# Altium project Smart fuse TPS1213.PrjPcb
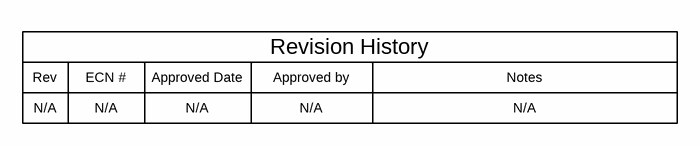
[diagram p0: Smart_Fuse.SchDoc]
TID: TIDA-020065; TechSupport: http://www.ti.com/support; SCH_Rev: E2; PRJ_Title: TPS1213-Q1+INA; PRJ_Number: TIDA-020065; PRJ_Engineer: David Martinez; PRJ_Customer: Public Release; PCB_Rev: E2; PCB_Layout: David Martinez; CopyrightYear: 2023
4 sheets, 114 parts. Net scope: global (net labels, ports and power ports of the same name join across sheets).
Board file: Smart_Fuse.PcbDoc
Sheets:
  Smart_Fuse.SchDoc
  Smart_Fuse_Schematic.SchDoc
  Smart_Fuse_MCU_Schematic.SchDoc
  Smart_Fuse_Hardware.SchDoc

## Sheet Smart_Fuse.SchDoc
size 431 x 279 mm; Date: Not shown in title block; ApprovedBy: Not shown in title block; CheckedBy: Not shown in title block; Author: Not shown in title block; CompanyName: Not shown in title block; Engineer: Not shown in title block; Organization: Not shown in title block; Address1: Not shown in title block; Address2: Not shown in title block; Address3: Not shown in title block; Address4: Not shown in title block; DocumentNumber: 1; Revision: Use project parameter SCH_Rev; SheetNumber: 1; SheetTotal: 4; PageSetup: Record=PageOptions¦CenterHorizontal=True¦CenterVertical=True¦PrintScale=1.00¦XCorrection=1.00¦YCorrection=1.00¦PrintKind=0¦BorderSize=5000000¦LeftOffset=0¦BottomOffset=0¦Orientation=2¦PaperLength=1000¦PaperWidth=1000¦Scale=100¦PaperSource=15¦PrintQuality=600¦MediaType=1¦DitherType=10¦PaperKind=Letter¦PrintScaleMode=1

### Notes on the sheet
- Rev
- N/A
- ECN #
- Approved Date
- Approved by
- Revision History
- Notes

## Sheet Smart_Fuse_Schematic.SchDoc: Main Page
size 431 x 279 mm; Date: Not shown in title block; ApprovedBy: Not shown in title block; CheckedBy: Not shown in title block; Author: Not shown in title block; CompanyName: Not shown in title block; DrawnBy: David Martinez; Engineer: Not shown in title block; Organization: Not shown in title block; Address1: Not shown in title block; Address2: Not shown in title block; Address3: Not shown in title block; Address4: Not shown in title block; DocumentNumber: 2; Revision: Use project parameter SCH_Rev; SheetNumber: 2; SheetTotal: 4; PageSetup: Record=PageOptions¦CenterHorizontal=True¦CenterVertical=True¦PrintScale=1.00¦XCorrection=1.00¦YCorrection=1.00¦PrintKind=0¦BorderSize=5000000¦LeftOffset=0¦BottomOffset=0¦Orientation=2¦PaperLength=1000¦PaperWidth=1000¦Scale=100¦PaperSource=15¦PrintQuality=600¦MediaType=1¦DitherType=10¦PaperKind=Letter¦PrintScaleMode=1
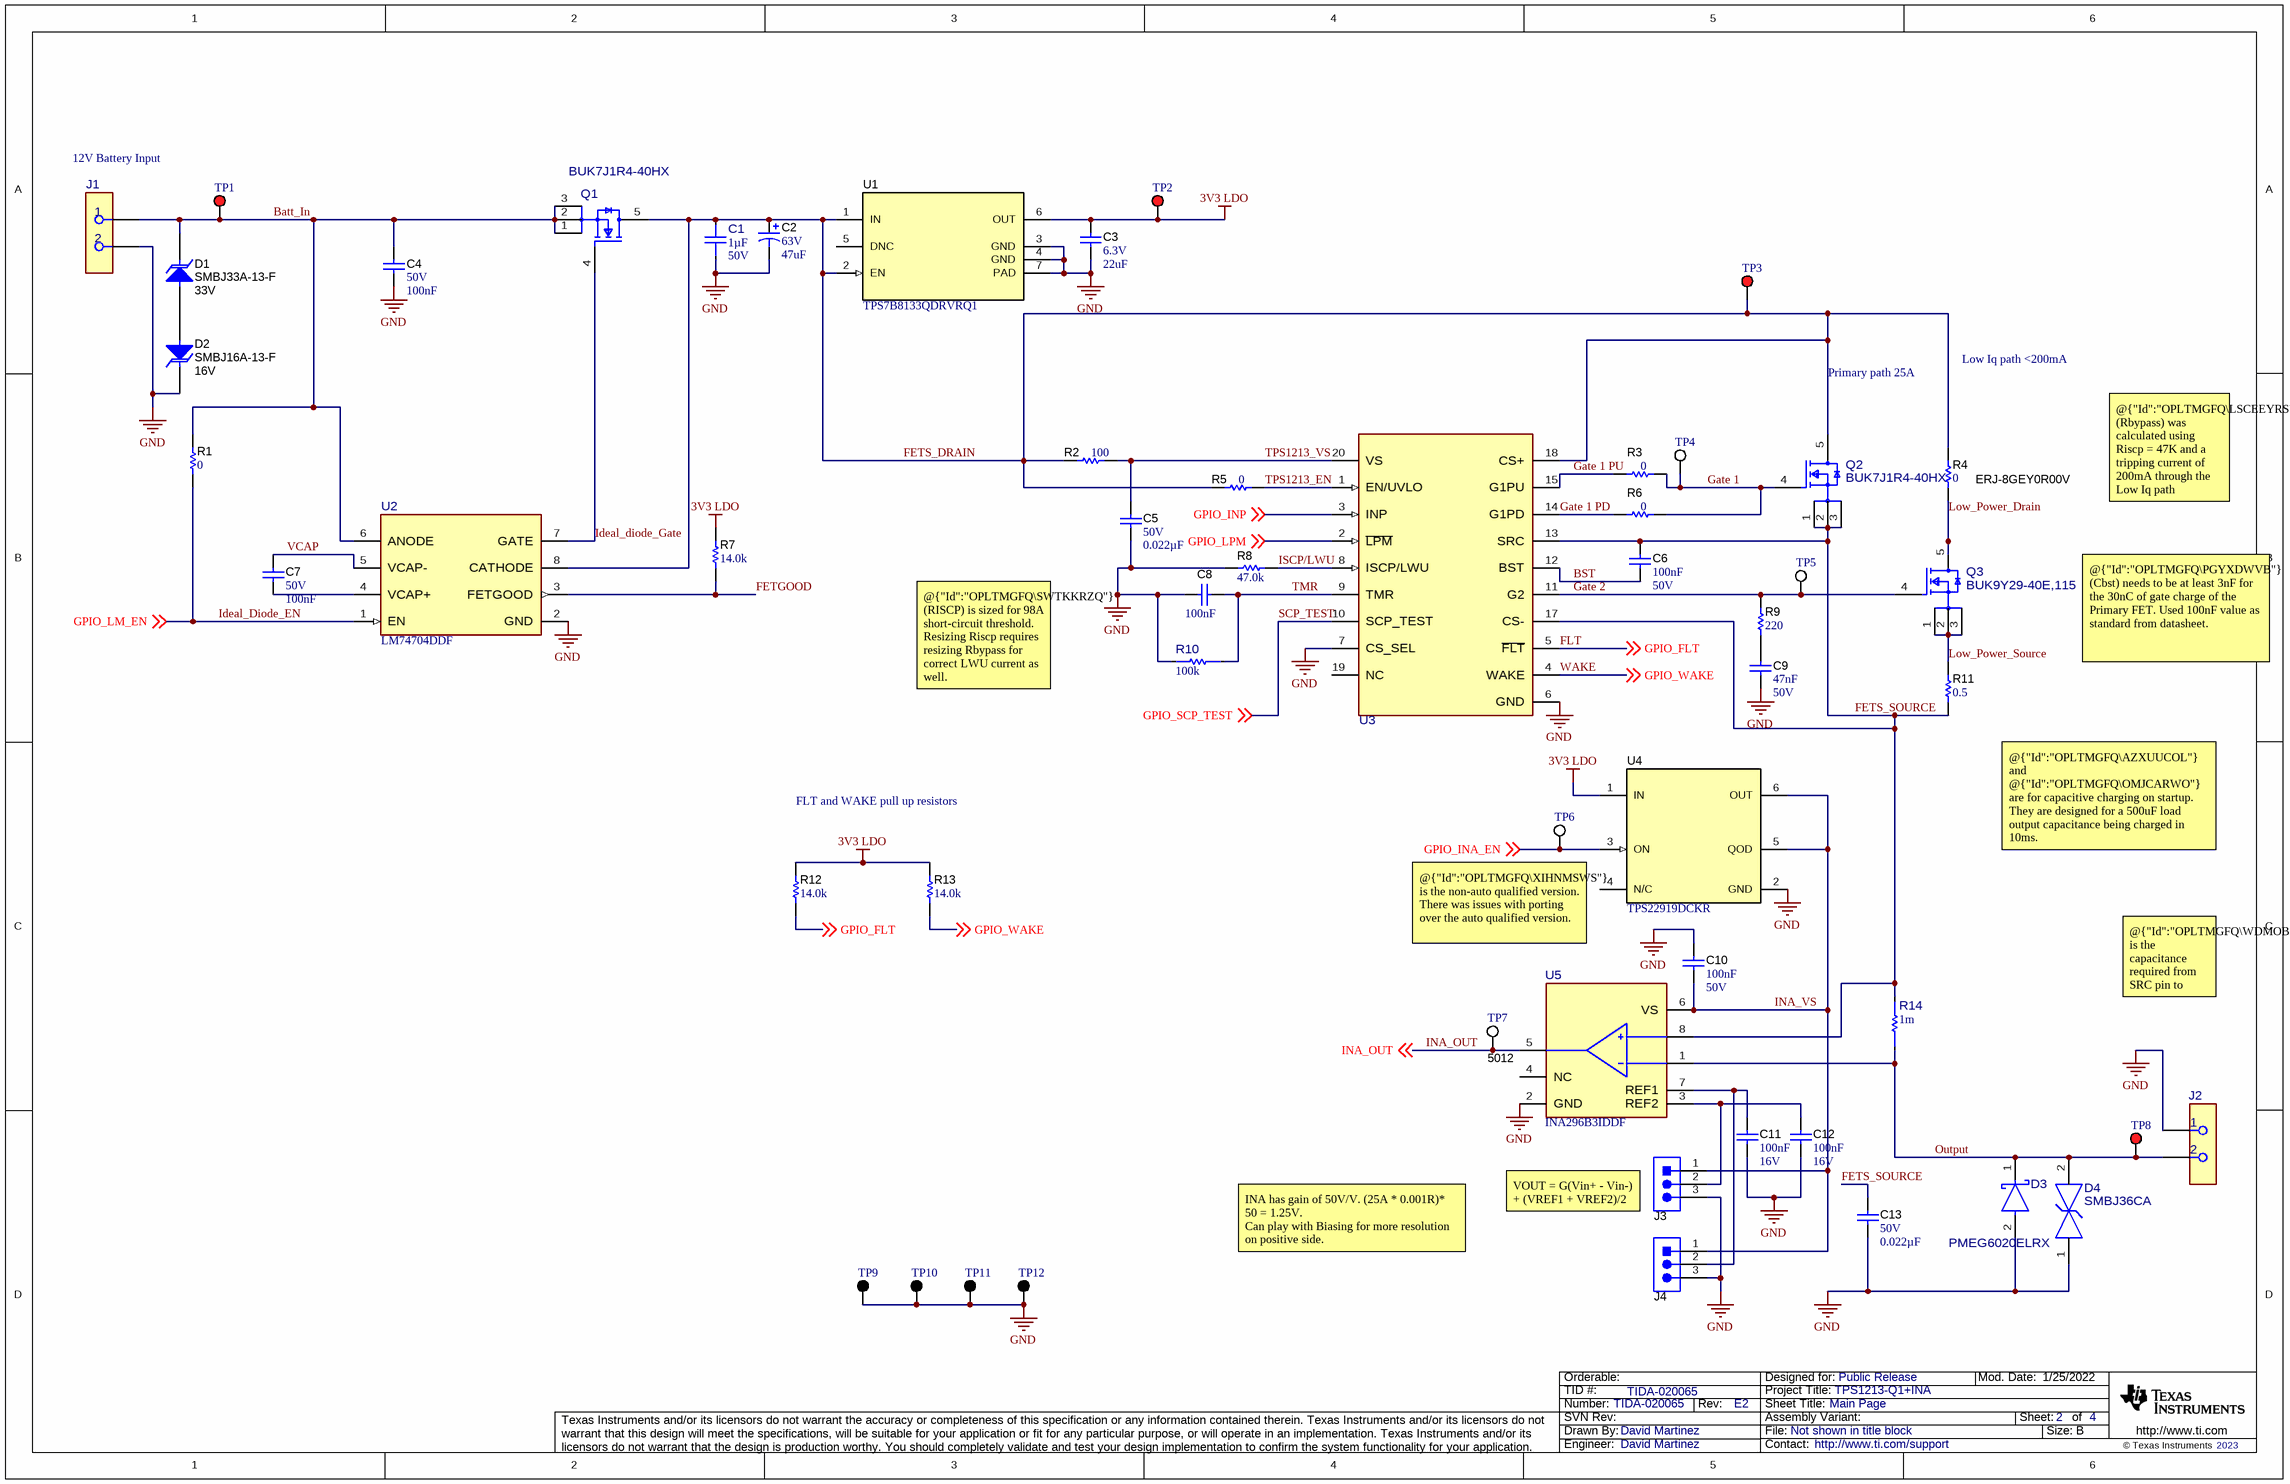
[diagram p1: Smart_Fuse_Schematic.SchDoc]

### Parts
C1  Cap_F: 1µF  VDC_V: 50V  [FP-UMK212B7105KGHT_0805-MFG]  (hidden comment: UMK212B7105KGHT)
C2  VDC_V: 63V  ValueDisplayed: 47uF  [SM_RADIAL_F]  (hidden comment: EEE-FK1J470P)
C3  VDC_V: 6.3V  ValueDisplayed: 22uF  [0805_HV]  (hidden comment: GCM21BD70J226ME36L)
C4  VDC_V: 50V  Cap_F: 100nF  [0603L]  (hidden comment: 06035C104K4Z4A)
C5  VDC_V: 50V  ValueDisplayed: 0.022µF  [0805_HV]  (hidden comment: CGA4J2C0G1H223J125AA)
C6  Cap_F: 100nF  VDC_V: 50V  [0603]  (hidden comment: 06035C104KAZ2A)
C7  VDC_V: 50V  Cap_F: 100nF  [0603L]  (hidden comment: 06035C104K4Z4A)
C8  Cap_F: 100nF  [0603]  (hidden comment: 06035C104KAZ2A)
C9  Cap_F: 47nF  VDC_V: 50V  [0603]  (hidden comment: CGA3E2X7R1H473K080AA)
C10  Cap_F: 100nF  VDC_V: 50V  [0603L]  (hidden comment: 06035C104KAZ2A)
C11  Cap_F: 100nF  VDC_V: 16V  [0603L]  (hidden comment: GRM188R71C104KA01D)
C12  Cap_F: 100nF  VDC_V: 16V  [0603L]  (hidden comment: GRM188R71C104KA01D)
C13  VDC_V: 50V  ValueDisplayed: 0.022µF  [0805_HV]  (hidden comment: CGA4J2C0G1H223J125AA)
D1  SMBJ33A-13-F  value 33V  [SMB]
D2  SMBJ16A-13-F  value 16V  [SMB]
D3  PMEG6020ELRX  [FP-PMEG6020ELRX_SOD123W-MFG]
D4  SMBJ36CA  [FP-SMBJ36CA_DO-214AA-0]
J1  691256610002  [FP-691256610002_HDR2-MFG]  (value not drawn)
J2  691256610002  [FP-691256610002_HDR2-MFG]  (value not drawn)
J3  TSW-103-07-T-S  [Samtec_TSW-103-07-T-S]  (value not drawn)
J4  TSW-103-07-T-S  [Samtec_TSW-103-07-T-S]  (value not drawn)
Q1  BUK7J1R4-40HX  [FP-BUK7J1R4-40HX_LFPAK56E-MFG]
Q2  BUK7J1R4-40HX  [FP-BUK7J1R4-40HX_LFPAK56E-MFG]
Q3  BUK9Y29-40E,115  [FP-BUK9Y29-40E,115_LFPAK56-MFG]
R1  ValueDisplayed: 0  [0603]  (hidden comment: ERJ-3GEY0R00V)
R2  ValueDisplayed: 100  [0603]  (hidden comment: RMCP0603JT100R)
R3  ValueDisplayed: 0  [0603]  (hidden comment: ERJ-3GEY0R00V)
R4  ERJ-8GEY0R00V  ValueDisplayed: 0  [1206]
R5  ValueDisplayed: 0  [0603]  (hidden comment: ERJ-3GEY0R00V)
R6  ValueDisplayed: 0  [0603]  (hidden comment: ERJ-3GEY0R00V)
R7  ValueDisplayed: 14.0k  [0603]  (hidden comment: CRCW060314K0FKEA)
R8  ValueDisplayed: 47.0k  [0603]  (hidden comment: RG1608P-473-B-T5)
R9  ValueDisplayed: 220  [0603]  (hidden comment: CRCW0603220RJNEA)
R10  value 100k  [FP-ERJ-PB3B1003V_0603-IPC_A]  (hidden comment: ERJ-PB3B1003V)
R11  ValueDisplayed: 0.5  [1206]  (hidden comment: CSR1206FKR500)
R12  ValueDisplayed: 14.0k  [0603]  (hidden comment: CRCW060314K0FKEA)
R13  ValueDisplayed: 14.0k  [0603]  (hidden comment: CRCW060314K0FKEA)
R14  Res_ohm: 1m  [FP-WSLF25121L000FEB_2512-MFG]  (hidden comment: WSLF25121L000FEB)
TP1  5010  [Keystone5010]  (value not drawn)
TP2  5010  [Keystone5010]  (value not drawn)
TP3  5010  [Keystone5010]  (value not drawn)
TP4  5012  [Keystone5012]  (value not drawn)
TP5  5012  [Keystone5012]  (value not drawn)
TP6  5012  [Keystone5012]  (value not drawn)
TP7  5012  [Keystone5012]
TP8  5010  [Keystone5010]  (value not drawn)
TP9  5011  [Keystone5011]  (value not drawn)
TP10  5011  [Keystone5011]  (value not drawn)
TP11  5011  [Keystone5011]  (value not drawn)
TP12  5011  [Keystone5011]  (value not drawn)
U1  TPS7B8133QDRVRQ1  [DRV0006A]
U2  LM74704DDF  [DDF0008A-MFG]
U3  TPS12130QDGXRQ1  [DGX0019A-MFG]  (value not drawn)
U4  TPS22919DCKR  [DCK0006A_N]
U5  INA296B3IDDF  [DDF0008A-MFG]

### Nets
3V3 LDO: C3.1 R7.2 R12.2 R13.2 TP2.1 U1.6(OUT) U4.1(IN)
GND: C1.1 C2.2(-) C3.2 C4.2 C5.2 C8.2 C9.2 C10.1 C11.2 C12.2 C13.2 D2.1(K) D3.2(ANODE) D4.1 J1.2 J2.1 J3.3 J4.3 R8.1 R10.2 TP9.1 TP10.1 TP11.1 TP12.1 U1.3(GND) U1.4(GND) U1.7(PAD) U2.2(GND) U3.6(GND) U3.7(CS_SEL) U4.2(GND) U5.2(GND)
Batt_In: C4.1 D1.1(K) J1.1 Q1.1(S) Q1.2(S) Q1.3(S) R1.2 TP1.1 U2.6(ANODE)
BST: C6.2 U3.12(BST)
FETGOOD: R7.1 U2.3(FETGOOD)
FETS_DRAIN: C1.2 C2.1(+) Q1.5(D) Q2.5(D) R2.1 R4.2 R5.1 TP3.1 U1.1(IN) U1.2(EN) U2.8(CATHODE) U3.18(CS+)
FETS_SOURCE: C6.1 C13.1 Q2.1(S) Q2.2(S) Q2.3(S) R11.1 R14.2 U3.13(SRC) U3.17(CS-) U5.8(IN+)
FLT: R12.1 U3.5(~{FLT}) ; off-sheet GPIO_FLT  [also labelled GPIO_FLT]
Gate 1: Q2.4(G) R3.2 R6.2 TP4.1
Gate 1 PD: R6.1 U3.14(G1PD)
Gate 1 PU: R3.1 U3.15(G1PU)
Gate 2: Q3.4(G) R9.2 TP5.1 U3.11(G2)
GPIO_INA_EN: TP6.1 U4.3(ON) ; off-sheet GPIO_INA_EN
GPIO_INP: U3.3(INP) ; off-sheet GPIO_INP
GPIO_LPM: U3.2(~{LPM}) ; off-sheet GPIO_LPM
GPIO_SCP_TEST: U3.10(SCP_TEST) ; off-sheet GPIO_SCP_TEST  [also labelled SCP_TEST]
GPIO_WAKE: R13.1 U3.4(WAKE) ; off-sheet GPIO_WAKE  [also labelled WAKE]
Ideal_Diode_EN: R1.1 U2.1(EN) ; off-sheet GPIO_LM_EN  [also labelled GPIO_LM_EN]
Ideal_diode_Gate: Q1.4(G) U2.7(GATE)
INA_OUT: TP7.1 U5.5(OUT) ; off-sheet INA_OUT
INA_VS: C10.2 J3.1 J4.1 U4.5(QOD) U4.6(OUT) U5.6(VS)
ISCP/LWU: R8.2 U3.8(ISCP/LWU)
Low_Power_Drain: Q3.5(D) R4.1
Low_Power_Source: Q3.1(S) Q3.2(S) Q3.3(S) R11.2
Output: D3.1(CATHODE) D4.2 J2.2 R14.1 TP8.1 U5.1(IN-)
TMR: C8.1 R10.1 U3.9(TMR)
TPS1213_EN: R5.2 U3.1(EN/UVLO)
TPS1213_VS: C5.1 R2.2 U3.20(VS)
VCAP: C7.1 U2.5(VCAP-)
NetC7_2: C7.2 U2.4(VCAP+)
NetC9_1: C9.1 R9.1
NetC11_1: C11.1 J4.2 U5.7(REF1)
NetC12_1: C12.1 J3.2 U5.3(REF2)
NetD1_2: D1.2(A) D2.2(A)

Not connected (* = marked no-connect by the designer): U1 5(DNC); U3 19(NC); U4 4(N/C); U5 4(NC)

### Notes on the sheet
- 12V Battery Input
- Low Iq path <200mA
- Primary path 25A
- @{"Id":"OPLTMGFQ\LSCEEYRS"} (Rbypass) was calculated using Riscp = 47K and a tripping current of 200mA through the Low Iq path
- @{"Id":"OPLTMGFQ\SWTKKRZQ"} (RISCP) is sized for 98A short-circuit threshold. Resizing Riscp requires resizing Rbypass for correct LWU current as well.
- @{"Id":"OPLTMGFQ\PGYXDWVB"} (Cbst) needs to be at least 3nF for the 30nC of gate charge of the Primary FET. Used 100nF value as standard from datasheet.
- FLT and WAKE pull up resistors
- @{"Id":"OPLTMGFQ\AZXUUCOL"} and @{"Id":"OPLTMGFQ\OMJCARWO"} are for capacitive charging on startup. They are designed for a 500uF load output capacitance being charged in 10ms.
- @{"Id":"OPLTMGFQ\XIHNMSWS"} is the non-auto qualified version. There was issues with porting over the auto qualified version.
- @{"Id":"OPLTMGFQ\WDMOBPKS"} is the capacitance required from SRC pin to GND.
- VOUT = G(Vin+ - Vin-) + (VREF1 + VREF2)/2
- INA has gain of 50V/V. (25A * 0.001R)* 50 = 1.25V.
  Can play with Biasing for more resolution on positive side.

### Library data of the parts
C1 = CMP-0098253-1: Multilayer Ceramic Capacitor 1 uF 50V X7R 10% SMD 0805 Automotive T/R; Manufacturer: Taiyo Yuden; Tolerance_%: 0.1%; AEC Qualified: Yes; SizeZ_mm: 1.35mm; ValueDisplayed: 1uF; Value: 1µF; TempCo: 0.15; AEC Grade: Grade 1
C2 = CMP-0011192-2: CAP, AL, 47 uF, 63 V, +/- 20%, 0.65 ohm, AEC-Q200 Grade 2, SMD; Manufacturer: Panasonic; TaMin_C: -55°C; ESR_ohm: 6.5d; Polarized: Y; SizeAreaWB_mm2: 123.6; U/M: EA; Value: 47uF; TaMax_C: 105°C; SizeZ_mm: 10.2; SizeX_mm: 10; SizeY_mm: 8.3; Cap_Case: F; SizeArea_mm2: 83; CompType: Capacitor; Cap_F: 47µF; IRMS_A: 2.5dA; AEC Grade: 2; AEC Category: Q200
C3 = CMP-0008015-1: CAP, CERM, 22 uF, 6.3 V, +/- 20%, X7T, AEC-Q200 Grade 1, 0805; Manufacturer: MuRata; TaMin_C: -55°C; Polarized: N; SizeAreaWB_mm2: 6.75; Value1: Unknown; U/M: EA; Value: 22uF; TaMax_C: 125°C; SizeZ_mm: 1.45; SizeX_mm: 2; SizeY_mm: 1.25; Cap_Case: 0805; SizeArea_mm2: 2.5; AEC Qualified: Y; Cap_F: 22µF; AEC Grade: 1; AEC Category: Q200
C4 C7 = CMP-0084736-1: CAP, CERM, 0.1 µF, 50 V,+/- 10%, X7R, AEC-Q200 Grade 0, 0603; Manufacturer: AVX; SizeX_mm: 1.6; AEC Qualified: Y; Value: 0.1uF; TaMin_C: -55°C; TaMax_C: 125°C; SizeY_mm: 0.8; SizeAreaWB_mm2: 4.68; AEC Grade: 0; SizeArea_mm2: 1.28; SizeZ_mm: 1; ValueDisplayed: 0.1µF; U/M: EA; Cap_Case: 0603; Polarized: N; AEC Category: Q200
C5 C13 = CMP-0079608-1: CAP, CERM, 0.022 µF, 50 V,+/- 5%, C0G/NP0, AEC-Q200 Grade 1, 0805; Manufacturer: TDK; TaMin_C: -55°C; Polarized: N; SizeAreaWB_mm2: 6.75; U/M: EA; Value: 0.022uF; TaMax_C: 125°C; SizeZ_mm: 1.45; SizeX_mm: 2; SizeY_mm: 1.25; Cap_Case: 0805; SizeArea_mm2: 2.5; AEC Qualified: Y; Cap_F: 22nF; AEC Grade: 1; AEC Category: Q200
C6 = CMP-0079095-1: CAP, CERM, 0.1 µF, 50 V,+/- 10%, X7R, AEC-Q200 Grade 1, 0603; Manufacturer: AVX; SizeAreaWB_mm2: 4.68; SizeArea_mm2: 1.28; AEC Qualified: Y; AEC Category: Q200; Value: 0.1uF; TaMax_C: 125°C; SizeZ_mm: 1; Polarized: N; TaMin_C: -55°C; SizeY_mm: 0.8; U/M: EA; SizeX_mm: 1.6; ValueDisplayed: 0.1µF
C8 = CMP-0079095-1: CAP, CERM, 0.1 µF, 50 V,+/- 10%, X7R, AEC-Q200 Grade 1, 0603; Manufacturer: AVX; SizeAreaWB_mm2: 4.68; SizeArea_mm2: 1.28; AEC Qualified: Y; AEC Category: Q200; Value: 0.1uF; TaMax_C: 125°C; SizeZ_mm: 1; Polarized: N; TaMin_C: -55°C; VDC_V: 50V; SizeY_mm: 0.8; U/M: EA; SizeX_mm: 1.6; ValueDisplayed: 0.1µF
C9 = CMP-0007079-4: CAP, CERM, 0.047 uF, 50 V, +/- 10%, X7R, AEC-Q200 Grade 1, 0603; Manufacturer: TDK; TaMin_C: -55°C; ESR_ohm: 49.007m; Polarized: N; SizeAreaWB_mm2: 4.68; Value1: 0.049007 ohm; U/M: EA; TaMax_C: 125°C; SizeZ_mm: 1; SizeX_mm: 1.6; SizeY_mm: 0.8; SizeArea_mm2: 1.28; AEC Qualified: Y; IRMS_A: 767.528mA; AEC Category: Q200
C10 = CMP-0079095-1: CAP, CERM, 0.1 µF, 50 V,+/- 10%, X7R, AEC-Q200 Grade 1, 0603; Manufacturer: AVX; SizeAreaWB_mm2: 4.68; SizeArea_mm2: 1.28; AEC Qualified: Y; AEC Category: Q200; Value: 0.1uF; TaMax_C: 125°C; SizeZ_mm: 1; Polarized: N; TaMin_C: -55°C; SizeY_mm: 0.8; U/M: EA; SizeX_mm: 1.6; Cap_Case: 0603; ValueDisplayed: 0.1µF
C11 C12 = CMP-0007378-5: CAP, CERM, 0.1 uF, 16 V, +/- 10%, X7R, 0603; Manufacturer: MuRata; TaMin_C: -55°C; Polarized: N; SizeAreaWB_mm2: 4.68; Value1: Unknown; U/M: EA; Value: 0.1uF; TaMax_C: 125°C; SizeZ_mm: 1; SizeX_mm: 1.6; SizeY_mm: 0.8; Cap_Case: 0603; SizeArea_mm2: 1.28; AEC Category: Q200
D1 = CMP-0005563-4: Diode, TVS, Uni, 33 V, 53.3 Vc, SMB; Manufacturer: Diodes Inc.; Vc: 53.3V; Value1: 600W; Vbr_Max: 42.2V; Vbr_Min: 36.7V; SizeX_mm: 5.6; SizeAreaWB_mm2: 44.156; AEC Category: Q101; SizeY_mm: 3.81; SizeZ_mm: 2.6; Ipp: 11.3A; SizeArea_mm2: 21.336
D2 = CMP-0005547-4: Diode, TVS, Uni, 16 V, 26 Vc, SMB; Manufacturer: Diodes Inc.; SizeArea_mm2: 21.336; SizeY_mm: 3.81; Vbr_Min: 17.8V; Ppk: 600W; AEC Category: Q101; SizeZ_mm: 2.6; Ipp: 23.1A; SizeAreaWB_mm2: 44.156; Vc: 26V; Vbr_Max: 20.5V; SizeX_mm: 5.6
D3 = CMP-0090247-1: Diode Schottky 60V 2A Surface Mount CFP3; Manufacturer: Nexperia; Cap_F: 110pF; SizeZ_mm: 1.1mm; TJmax_C: 175°C; AEC Grade: Grade 0; Forward Current: 2.83A; Max Surge Forward Current: 50A; AEC Qualified: Yes; TaMin_C: -55°C; Peak Reverse Current: 0.09uA; TaMax_C: +175°C
D4 = CMP-0086728-1: Diode TVS Single Bi-Dir 36V 600W 2-Pin SMB; Manufacturer: Littelfuse; SizeZ_mm: 2.61mm; Ipp: 10.4µA
J1 J2 = CMP-0086764-1: 2 Position Wire to Board Terminal Block Horizontal with Board 0.400" (10.16mm) Through Hole; Manufacturer: Wurth; Current_A: 57A; Voltage_V: 750V; ContactFinish: Zinc; Row_Count: 1
J3 J4 = CMP-0075530-2: Header, 2.54 mm, 3x1, Tin, TH; Manufacturer: Samtec; Pitch_mm: 2.54; Cert_VDE: N; Gender: Male; Cert_CSA: Y; Voltage_V: 550V; Green_REACh: Passed; Current_A: 6.3A; Green_Lifecycle: Active; Row_Count: 1
Q1 Q2 = CMP-0098150-1: Trans MOSFET N-CH 40V 190A Automotive 5-Pin(4+Tab) LFPAK T/R; Manufacturer: Nexperia; Drain To Source Breakdown Voltage: 42V; Threshold Vgs Max: 3.6V; Turn On Delay Time: 19ns; ChMode: False; Standoff Height: 0mm; Rdson45_ohm: 1.06m; Power_W: 395W; TJmax_C: +175°C; Pulse Drain Current: 600A; QgTyp_nC: 73nC @ 10V; Vgs_V: 20V; AEC Grade: Grade 0; AEC Qualified: Yes; Turn Off Delay Time: 43ns; VdsMax_V: 1.2V; Input Capacitace At Vds: 5436pF @ 25V; Number Of Channels: 1; SizeZ_mm: 1.25mm; Reverse Recovery Charge: 39nC; Reverse Recovery Time: 37ns; Typ Forward Diode Voltage: 0.8V; Threshold Vgs Min: 2.4V
Q3 = CMP-0098178-1: Trans MOSFET N-CH 40V 25A Automotive 5-Pin(4+Tab) LFPAK T/R; Manufacturer: Nexperia; ChMode: False; Turn On Delay Time: 6ns; Pulse Drain Current: 101A; Power_W: 37W; TJmax_C: +175°C; Number Of N Channels: 1; QgTyp_nC: 5nC @ 5V; Rdson45_ohm: 25.8m; Reverse Recovery Time: 14.3ns; Standoff Height: 0mm; Typ Forward Diode Voltage: 0.84V; Vgs_V: 10V; SizeZ_mm: 1.2mm; AEC Qualified: Yes; Threshold Vgs Min: 1.4V; AEC Grade: Grade 0; Threshold Vgs Max: 2.1V; Turn Off Delay Time: 9ns; Reverse Recovery Charge: 6.6nC; Input Capacitace At Vds: 498pF @ 25V; VdsMax_V: 1.2V
R1 R3 R5 R6 = CMP-0025874-4: RES, 0, 5%, 0.1 W, AEC-Q200 Grade 0, 0603; Manufacturer: Panasonic; Power_W: 100mW; TempCo: 600 ppm/C; Value_Code: 0000; Value: 0; EIA_Code: E24; SizeX_mm: 1.6; SizeY_mm: 0.8; SizeZ_mm: 1; Value2: 0.1W; SizeArea_mm2: 1.28; AEC Qualified: Y; VDC_V: 50V; AEC Category: Q200; SizeAreaWB_mm2: 4.68
R2 = CMP-0860543-1: RES, 100, 5%, 0.25 W, AEC-Q200 Grade 0, 0603; Manufacturer: Stackpole Electronics Inc; AEC Category: Q200; AEC Grade: 0; SizeAreaWB_mm2: 4.68; TempCo: 100 ppm/C; SizeY_mm: 0.8; AEC Qualified: Y; Value: 100; Value2: 0.25W; SizeX_mm: 1.6; SizeArea_mm2: 1.28; SizeZ_mm: 1; EIA_Code: E24; Power_W: 250mW; Value_Code: 100R
R4 = CMP-0018748-3: RES, 0, 5%, 0.25 W, AEC-Q200 Grade 0, 1206; Manufacturer: Panasonic; Power_W: 250mW; TempCo: 600 ppm/C; Value_Code: 0000; Value: 0; EIA_Code: E24; SizeX_mm: 3.2; SizeY_mm: 1.6; SizeZ_mm: 1.35; Value2: 0.25W; SizeArea_mm2: 5.12; AEC Qualified: Y; VDC_V: 200V; AEC Category: Q200; SizeAreaWB_mm2: 10.92
R7 R12 R13 = CMP-0022054-4: RES, 14.0 k, 1%, 0.1 W, AEC-Q200 Grade 0, 0603; Manufacturer: Vishay-Dale; Power_W: 100mW; TempCo: 100 ppm/C; Value_Code: 14k0; Value: 14.0k; EIA_Code: E96; Res_ohm: 14k; SizeX_mm: 1.6; SizeY_mm: 0.8; SizeZ_mm: 1; Value2: 0.1W; SizeArea_mm2: 1.28; AEC Qualified: Y; VDC_V: 75V; AEC Category: Q200; AEC Grade: 0
R8 = CMP-0023556-3: RES, 47.0 k, 0.1%, 0.1 W, 0603; Manufacturer: Susumu Co Ltd; Power_W: 100mW; TempCo: 25 ppm/C; Value_Code: 47k0; U/M: EA; Value: 47.0k; EIA_Code: E192; Res_ohm: 47k; SizeX_mm: 1.6; SizeY_mm: 0.8; SizeZ_mm: 1; Value2: 0.1W; SizeArea_mm2: 1.28; VDC_V: 75V; AEC Category: Q200
R9 = CMP-0025756-4: RES, 220, 5%, 0.1 W, AEC-Q200 Grade 0, 0603; Manufacturer: Vishay-Dale; Power_W: 100mW; TempCo: 200 ppm/C; Value_Code: 220R; Value: 220; EIA_Code: E24; SizeX_mm: 1.6; SizeY_mm: 0.8; SizeZ_mm: 1; Value2: 0.1W; SizeArea_mm2: 1.28; AEC Qualified: Y; VDC_V: 75V; AEC Category: Q200; AEC Grade: 0
R10 = CMP-0092407-1: Res Thick Film 0603 100K Ohm 0.1% 0.2W(1/5W) ±50ppm/°C Pad SMD Automotive T/R; Manufacturer: Panasonic; Power_W: 200mW; VDC_V: 150V; AEC Qualified: Yes; SizeZ_mm: 0.55mm; AEC Grade: Grade 0
R11 = CMP-0017270-2: RES, 0.5, 1%, 0.5 W, 1206; Manufacturer: Stackpole Electronics Inc; Power_W: 500mW; TempCo: 100 ppm/C; Value_Code: R500; U/M: EA; Value: 0.5; SizeX_mm: 3.2; SizeY_mm: 1.6; SizeZ_mm: 1.35; Value2: 0.5W; SizeArea_mm2: 5.12; AEC Category: Q200
R14 = CMP-0089827-1: 1 mOhms ±1% 5W Chip Resistor 2512 (6432 Metric) Automotive AEC-Q200, Current Sense, Moisture Resistant, Pulse Withstanding Metal Element; Manufacturer: Vishay; SizeZ_mm: 0.81mm; AEC Grade: Grade 0; Standoff Height: 0.32mm; AEC Qualified: Yes; TempCo: 170ppm/°C
TP1-TP3 TP8 = CMP-0055147-2: Test Point, Multipurpose, Red, TH; Manufacturer: Keystone Electronics; CT: TRUE; ContactFinish: Silver; Green_Lifecycle: Active; CNHeader: FALSE; Green_REACh: Passed
TP4-TP7 = CMP-0055149-2: Test Point, Multipurpose, White, TH; Manufacturer: Keystone Electronics; ContactFinish: Silver; CT: TRUE; CNHeader: FALSE; Green_Lifecycle: Active; Green_REACh: Passed
TP9-TP12 = CMP-0055148-2: Test Point, Multipurpose, Black, TH; Manufacturer: Keystone Electronics; CNHeader: FALSE; ContactFinish: Silver; Green_REACh: Passed; Green_Lifecycle: Active; CT: TRUE
U1 = CMP-0860463-2: Automotive 150-mA high-voltage ultra-low-IQ low-dropout (LDO) linear regulator, DRV0006A (WSON-6); Alternate Manufacturer: Texas Instruments; AEC Qualified: Y; SizeY_mm: 2; SizeZ_mm: 0.8; AEC Category: Q200; CompType: IC; SizeArea_mm2: 4; SizeAreaWB_mm2: 9
U2 = CMP-0097715-1: Ideal Diode Controller with FET Good Output, SOT23-8; Manufacturer: Texas Instruments; Number Of Outputs: 1; AEC Qualified: Yes; Standoff Height: 0mm; Nominal Supply Current: 80uA; TaMin_C: -40°C; Max Supply Voltage: 60V; SizeZ_mm: 1.1mm; AEC Grade: Grade 1; TJmax_C: +150°C; Min Supply Voltage: 4V; TaMax_C: +125°C
U3 = CMP-0098484-1: 45-V Low IQ Automotive High Side Switch Controller with Low Power Mode and Adjustable Load Wakeup Trigger; Manufacturer: Texas Instruments; SizeZ_mm: 1.1mm; AEC Qualified: Yes; AEC Grade: Grade 1; Max Supply Voltage: 40V; Min Supply Voltage: 3V; Nominal Supply Current: 28-36uA; Number Of Outputs: 1; Standoff Height: 0.05mm; TJmax_C: +150°C
U4 = CMP-0081108-1: 5.5-V, 1.5-A, 100-mohm Load Switch with Output Discharge, DCK0006A (SOT-SC70-6); Alternate PartNumber: TPS22919DCKT; Alternate Manufacturer: Texas Instruments; SizeAreaWB_mm2: 9.3; SizeZ_mm: 1.1; SizeX_mm: 2.1; SizeY_mm: 2; SizeArea_mm2: 4.2; CompType: IC; AEC Qualified: N; AEC Category: Q200
U5 = CMP-0096516-2: -4-V to 110-V, Bidirectional, 1-MHz, 5-V/μs, Ultra-Precise Current Sense Amplifier; Manufacturer: Texas Instruments; Input Bias Current: 40uA; Voltage Gain: 0.05V/mV; AEC Category: Q200; Response Time: 1.5us; Nominal Supply Current: 2.5mA; TaMax_C: +125°C; Bandwidth: 1MHz; TaMin_C: -40°C; TJmax_C: +150°C; Input Offset Voltage: 0.025mV; Standoff Height: 0mm; Number Of Channels: 1; SizeZ_mm: 1.1mm; Max Supply Voltage: 20V; AEC Qualified: No; CompType: IC; Min Supply Voltage: 2.7V

## Sheet Smart_Fuse_MCU_Schematic.SchDoc: MSPM0
size 431 x 279 mm; Date: Not shown in title block; ApprovedBy: Not shown in title block; CheckedBy: Not shown in title block; Author: Not shown in title block; CompanyName: Not shown in title block; DrawnBy: Robert Smith; Engineer: Not shown in title block; Organization: Not shown in title block; Address1: Not shown in title block; Address2: Not shown in title block; Address3: Not shown in title block; Address4: Not shown in title block; DocumentNumber: 1; Revision: Use project parameter SCH_Rev; SheetNumber: 3; SheetTotal: 4; PageSetup: Record=PageOptions¦CenterHorizontal=True¦CenterVertical=True¦PrintScale=1.00¦XCorrection=1.00¦YCorrection=1.00¦PrintKind=0¦BorderSize=5000000¦LeftOffset=0¦BottomOffset=0¦Orientation=2¦PaperLength=1000¦PaperWidth=1000¦Scale=100¦PaperSource=15¦PrintQuality=600¦MediaType=1¦DitherType=10¦PaperKind=Letter¦PrintScaleMode=1
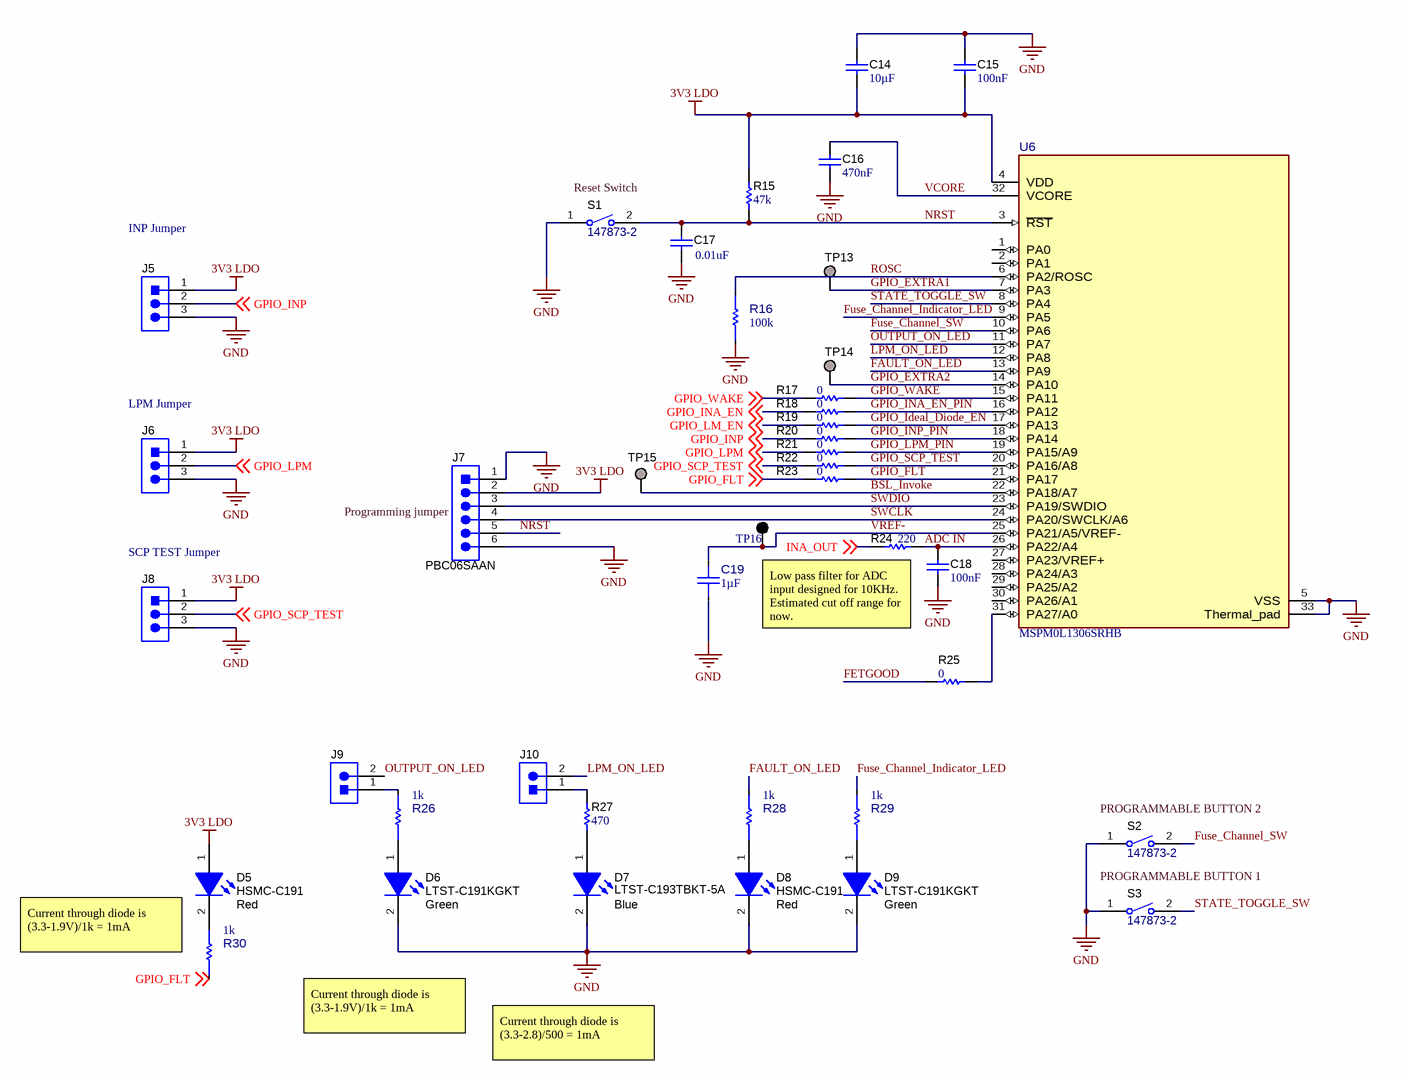
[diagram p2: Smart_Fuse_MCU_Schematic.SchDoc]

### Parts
C14  Cap_F: 10µF  [0805_HV]  (hidden comment: JMJ212CB7106KGHT)
C15  Cap_F: 100nF  [0603]  (hidden comment: 06035C104KAZ2A)
C16  Cap_F: 470nF  [0603]  (hidden comment: CGA3E3X7R1H474M080AE)
C17  ValueDisplayed: 0.01uF  [0603]  (hidden comment: C0603C103J3GECAUTO)
C18  Cap_F: 100nF  [0603]  (hidden comment: 06035C104KAZ2A)
C19  Cap_F: 1µF  [FP-UMK212B7105KGHT_0805-MFG]  (hidden comment: UMK212B7105KGHT)
D5  HSMC-C191  value Red  [HSMx-C191_Red]
D6  LTST-C191KGKT  value Green  [LTST-C191_Green]
D7  LTST-C193TBKT-5A  value Blue  [LTST-C193_Blue]
D8  HSMC-C191  value Red  [HSMx-C191_Red]
D9  LTST-C191KGKT  value Green  [LTST-C191_Green]
J5  TSW-103-07-T-S  [Samtec_TSW-103-07-T-S]  (value not drawn)
J6  TSW-103-07-T-S  [Samtec_TSW-103-07-T-S]  (value not drawn)
J7  PBC06SAAN  [Sullins_PxC06SAAN]
J8  TSW-103-07-T-S  [Samtec_TSW-103-07-T-S]  (value not drawn)
J9  SL 11 112 02G  [Fischer_SL-11-112-02G]  (value not drawn)
J10  SL 11 112 02G  [Fischer_SL-11-112-02G]  (value not drawn)
R15  ValueDisplayed: 47k  [0603]  (hidden comment: CRCW060347K0JNEA)
R16  value 100k  [FP-ERJ-PB3B1003V_0603-MFG]  (hidden comment: ERJ-PB3B1003V)
R17  ValueDisplayed: 0  [0603]  (hidden comment: ERJ-3GEY0R00V)
R18  ValueDisplayed: 0  [0603]  (hidden comment: ERJ-3GEY0R00V)
R19  ValueDisplayed: 0  [0603]  (hidden comment: ERJ-3GEY0R00V)
R20  ValueDisplayed: 0  [0603]  (hidden comment: ERJ-3GEY0R00V)
R21  ValueDisplayed: 0  [0603]  (hidden comment: ERJ-3GEY0R00V)
R22  ValueDisplayed: 0  [0603]  (hidden comment: ERJ-3GEY0R00V)
R23  ValueDisplayed: 0  [0603]  (hidden comment: ERJ-3GEY0R00V)
R24  ValueDisplayed: 220  [0603]  (hidden comment: RG1608P-221-B-T5)
R25  ValueDisplayed: 0  [0603]  (hidden comment: ERJ-3GEY0R00V)
R26  value 1k  [FP-RNCF0603TKW1K00_0603-MFG]  (hidden comment: RNCF0603TKW1K00)
R27  ValueDisplayed: 470  [0603]  (hidden comment: CRCW0603470RJNEA)
R28  value 1k  [FP-RNCF0603TKW1K00_0603-MFG]  (hidden comment: RNCF0603TKW1K00)
R29  value 1k  [FP-RNCF0603TKW1K00_0603-MFG]  (hidden comment: RNCF0603TKW1K00)
R30  value 1k  [FP-RNCF0603TKW1K00_0603-MFG]  (hidden comment: RNCF0603TKW1K00)
S1  147873-2  [SW_147873-2]
S2  147873-2  [SW_147873-2]
S3  147873-2  [SW_147873-2]
TP13  TP_SM_1MM  [TP_SM_1MM]  (value not drawn)  (no BOM)
TP14  TP_SM_1MM  [TP_SM_1MM]  (value not drawn)  (no BOM)
TP15  TP_SM_1MM  [TP_SM_1MM]  (value not drawn)  (no BOM)
TP16  5011  [Keystone5011]  (value not drawn)
U6  MSPM0L1306SRHB  [RHB0032N-MFG]

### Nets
3V3 LDO: C14.2 C15.2 D5.1(A) J5.1 J6.1 J7.2 J8.1 R15.2 U6.4(VDD)
GND: C14.1 C15.1 C16.2 C17.2 C18.2 C19.1 D6.2(K) D7.2(K) D8.2(K) D9.2(K) J5.3 J6.3 J7.1 J7.6 J8.3 R16.1 S1.1 S2.1 S3.1 U6.5(VSS) U6.33(Thermal_pad)
ADC IN: C18.1 R24.2 U6.26(PA22/A4)
BSL_Invoke: TP15.1 U6.22(PA18/A7)
FAULT_ON_LED: R28.2 U6.13(PA9)
FETGOOD: R25.1
Fuse_Channel_Indicator_LED: R29.2 U6.9(PA5)
Fuse_Channel_SW: S2.2 U6.10(PA6)
GPIO_EXTRA1: TP13.1 U6.7(PA3)
GPIO_EXTRA2: TP14.1 U6.14(PA10)
GPIO_FLT: R23.1 R23.2 R30.1 U6.21(PA17) ; off-sheet GPIO_FLT  [project net FLT]
GPIO_Ideal_Diode_EN: R19.2 U6.17(PA13)
GPIO_INA_EN: R18.1 ; off-sheet GPIO_INA_EN
GPIO_INA_EN_PIN: R18.2 U6.16(PA12)
GPIO_INP: J5.2 R20.1 ; off-sheet GPIO_INP
GPIO_INP_PIN: R20.2 U6.18(PA14)
GPIO_LM_EN: R19.1 ; off-sheet GPIO_LM_EN  [project net Ideal_Diode_EN]
GPIO_LPM: J6.2 R21.1 ; off-sheet GPIO_LPM
GPIO_LPM_PIN: R21.2 U6.19(PA15/A9)
GPIO_SCP_TEST: J8.2 R22.1 R22.2 U6.20(PA16/A8) ; off-sheet GPIO_SCP_TEST
GPIO_WAKE: R17.1 R17.2 U6.15(PA11) ; off-sheet GPIO_WAKE
INA_OUT: R24.1 ; off-sheet INA_OUT
LPM_ON_LED: J10.2 U6.12(PA8)
NRST: C17.1 J7.5 R15.1 S1.2 U6.3(~{RST})
OUTPUT_ON_LED: J9.2 U6.11(PA7)
ROSC: R16.2 U6.6(PA2/ROSC)
STATE_TOGGLE_SW: S3.2 U6.8(PA4)
SWCLK: J7.4 U6.24(PA20/SWCLK/A6)
SWDIO: J7.3 U6.23(PA19/SWDIO)
VCORE: C16.1 U6.32(VCORE)
VREF-: C19.2 TP16.1 U6.25(PA21/A5/VREF-)
NetD5_2: D5.2(K) R30.2
NetD6_1: D6.1(A) R26.1
NetD7_1: D7.1(A) R27.1
NetD8_1: D8.1(A) R28.1
NetD9_1: D9.1(A) R29.1
NetJ9_1: J9.1 R26.2
NetJ10_1: J10.1 R27.2
NetR25_2: R25.2 U6.31(PA27/A0)

Not connected (* = marked no-connect by the designer): U6 1(PA0) 2(PA1) 27(PA23/VREF+) 28(PA24/A3) 29(PA25/A2) 30(PA26/A1)

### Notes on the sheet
- INP Jumper
- (near S1) Reset Switch
- (near J6) LPM Jumper
- (near J8) SCP TEST Jumper
- (near J7) Programming jumper
- (near R24) Low pass filter for ADC input designed for 10KHz. Estimated cut off range for now.
- (near S2) PROGRAMMABLE BUTTON 2
- PROGRAMMABLE BUTTON 1
- Current through diode is (3.3-1.9V)/1k = 1mA
- Current through diode is (3.3-2.8)/500 = 1mA

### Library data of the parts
C14 = CMP-0081188-1: CAP, CERM, 10 µF, 6.3 V,+/- 10%, X7R, AEC-Q200 Grade 1, 0805; Manufacturer: Taiyo Yuden; TaMin_C: -55°C; Polarized: N; SizeAreaWB_mm2: 6.75; U/M: EA; Value: 10uF; TaMax_C: 125°C; SizeZ_mm: 1.45; SizeX_mm: 2; SizeY_mm: 1.25; Cap_Case: 0805; Value2: 6.3V; SizeArea_mm2: 2.5; AEC Qualified: Y; AEC Grade: 1; AEC Category: Q200
C15 C18 = CMP-0079095-1: as C8 on sheet Smart_Fuse_Schematic
C16 = CMP-0007098-4: CAP, CERM, 0.47 uF, 50 V, +/- 20%, X7R, AEC-Q200 Grade 1, 0603; Manufacturer: TDK; TaMin_C: -55°C; Polarized: N; SizeAreaWB_mm2: 4.68; Value1: Unknown; U/M: EA; Value: 0.47uF; TaMax_C: 125°C; SizeZ_mm: 1; SizeX_mm: 1.6; SizeY_mm: 0.8; Value2: 50V; SizeArea_mm2: 1.28; AEC Qualified: Y; AEC Category: Q200
C17 = CMP-0006849-4: CAP, CERM, 0.01 uF, 25 V, +/- 5%, C0G/NP0, AEC-Q200 Grade 1, 0603; Manufacturer: Kemet; TaMin_C: -55°C; Polarized: N; SizeAreaWB_mm2: 4.68; Value1: Unknown; U/M: EA; Value: 0.01uF; TaMax_C: 125°C; SizeZ_mm: 1; SizeX_mm: 1.6; SizeY_mm: 0.8; Value2: 25V; SizeArea_mm2: 1.28; AEC Qualified: Y; Cap_F: 10nF; AEC Category: Q200
C19 = CMP-0098253-1: as C1 on sheet Smart_Fuse_Schematic
D5 D8 = CMP-0078541-2: LED, Red, SMD; Manufacturer: Avago; Vf_V: 1.9V; SizeX_mm: 1.6; SizeY_mm: 0.8; Tjmax_C: 95°C; Io_A: 20mA; SizeAreaWB_mm2: 4.68; Value1: W; Angle: 170; SizeArea_mm2: 1.28; Vr_V: 5V; Type: AlInGaP; SizeZ_mm: 0.7
D6 D9 = CMP-0078478-2: LED, Green, SMD; Manufacturer: Lite-On; Value2: 2V; Vr_V: 5V; Ir_A: 10µA; Value1: 0.075W; Tjmax_C: 85°C; Green_Lifecycle: Not Set; Angle: 130; Type: AlInGaP; Power_TotalModule: 75mW; Io_A: 30mA; Green_REACh: Incomplete
D7 = CMP-0002938-3: LED, Blue, SMD; Manufacturer: Lite-On; Angle: 130; Power_TotalModule: 76mW; Type: InGaN; Tjmax_C: 80°C; Value1: 0.076W; Io_A: 5mA; Ir_A: 10µA; LuminousIntensity_IV: 15; Value2: 2.8V
J5 J6 J8 = CMP-0075530-2: as J3 on sheet Smart_Fuse_Schematic
J7 = CMP-0054603-1: Header, 2.54mm, 6x1, Gold, TH; Manufacturer: Sullins Connector Solutions; CNHeader: TRUE; Current_A: 3A; Green_Lifecycle: Not Set; Shrouded: N; Gender: Male; Green_REACh: Incomplete; Row_Count: 1; Pitch_mm: 2.54; CT: FALSE; Cert_UL: Y
J9 J10 = CMP-0075049-1: Header, 2.54mm, 2x1, Gold, TH; Manufacturer: Fischer Elektronik; CT: False; CNHeader: True
R15 = CMP-0025814-4: RES, 47 k, 5%, 0.1 W, AEC-Q200 Grade 0, 0603; Manufacturer: Vishay-Dale; Power_W: 100mW; TempCo: 200 ppm/C; Value_Code: 47k0; Value: 47k; EIA_Code: E24; SizeX_mm: 1.6; SizeY_mm: 0.8; SizeZ_mm: 1; Value2: 0.1W; SizeArea_mm2: 1.28; AEC Qualified: Y; VDC_V: 75V; AEC Category: Q200; AEC Grade: 0
R16 = CMP-0092407-1: as R10 on sheet Smart_Fuse_Schematic
R17-R23 R25 = CMP-0025874-4: as R1 on sheet Smart_Fuse_Schematic
R24 = CMP-0023472-3: RES, 220, 0.1%, 0.1 W, 0603; Manufacturer: Susumu Co Ltd; Power_W: 100mW; TempCo: 25 ppm/C; Value_Code: 220R; U/M: EA; Value: 220; SizeX_mm: 1.6; SizeY_mm: 0.8; SizeZ_mm: 1; Value2: 0.1W; SizeArea_mm2: 1.28; VDC_V: 75V; AEC Category: Q200
R26 R28-R30 = CMP-0091933-1: 1 kOhms ±0.01% 0.1W, 1/10W Chip Resistor 0603 (1608 Metric) Automotive AEC-Q200 Thin Film; Manufacturer: Stackpole Electronics; VDC_V: 75V; AEC Qualified: Yes; Power_W: 100mW; AEC Grade: Grade 0; TempCo: 2ppm/°C; SizeZ_mm: 0.55mm
R27 = CMP-0025813-4: RES, 470, 5%, 0.1 W, AEC-Q200 Grade 0, 0603; Manufacturer: Vishay-Dale; Power_W: 100mW; TempCo: 200 ppm/C; Value_Code: 470R; Value: 470; EIA_Code: E24; SizeX_mm: 1.6; SizeY_mm: 0.8; SizeZ_mm: 1; Value2: 0.1W; SizeArea_mm2: 1.28; AEC Qualified: Y; VDC_V: 75V; AEC Category: Q200; AEC Grade: 0
S1-S3 = CMP-0002294-1: Switch, SPST, Off-On, 50 mA,24V, SMD; Manufacturer: TE Connectivity; CurrentRating_mA: 50A; PositionCount: 1; SizeX_mm: 6.8; SizeY_mm: 3.5; SizeZ_mm: 4.65; SizeArea_mm2: 23.8; SizeAreaWB_mm2: 48.4
TP13-TP15 = CMP-0003825-1: 1mm Test Point, SMT; Manufacturer: Any
TP16 = CMP-0055148-2: as TP9 on sheet Smart_Fuse_Schematic
U6 = CMP-0093968-1: MSPM0L130x Mixed-Signal Microcontrollers; Manufacturer: Texas Instruments; Number Of Pwm Channels: 8; TJmax_C: +130°C; Interface: I2C,SPI,UART,LIN,IrDA,SMBus; Number Of I2C Channels: 2; Memory Size: 64KBytes; Core Architecture: ARM Cortex-M0+; Number Of Spi Channels: 1; Min Supply Voltage: 1.62V; Ram Size: 4KBytes; Data Bus Width: 32bits; TaMax_C: +125°C; Frequency_Fixed: 32MHz; Memory Type: FLASH; Number Of Adc Channels: 10; Standoff Height: 0mm; AEC Qualified: No; Number Of I/Os: 28; TaMin_C: -40°C; SizeZ_mm: 1mm; Max Supply Voltage: 3.6V; Number Of Timers/Counters: 4

## Sheet Smart_Fuse_Hardware.SchDoc: Hardware
size 431 x 279 mm; Date: Not shown in title block; ApprovedBy: Not shown in title block; CheckedBy: Not shown in title block; Author: Not shown in title block; CompanyName: Not shown in title block; DrawnBy: Robert Smith; Engineer: Not shown in title block; Organization: Not shown in title block; Address1: Not shown in title block; Address2: Not shown in title block; Address3: Not shown in title block; Address4: Not shown in title block; DocumentNumber: 3; Revision: Use project parameter SCH_Rev; SheetNumber: 4; SheetTotal: 4; PageSetup: Record=PageOptions¦CenterHorizontal=True¦CenterVertical=True¦PrintScale=1.00¦XCorrection=1.00¦YCorrection=1.00¦PrintKind=0¦BorderSize=5000000¦LeftOffset=0¦BottomOffset=0¦Orientation=2¦PaperLength=1000¦PaperWidth=1000¦Scale=100¦PaperSource=15¦PrintQuality=600¦MediaType=1¦DitherType=10¦PaperKind=Letter¦PrintScaleMode=1
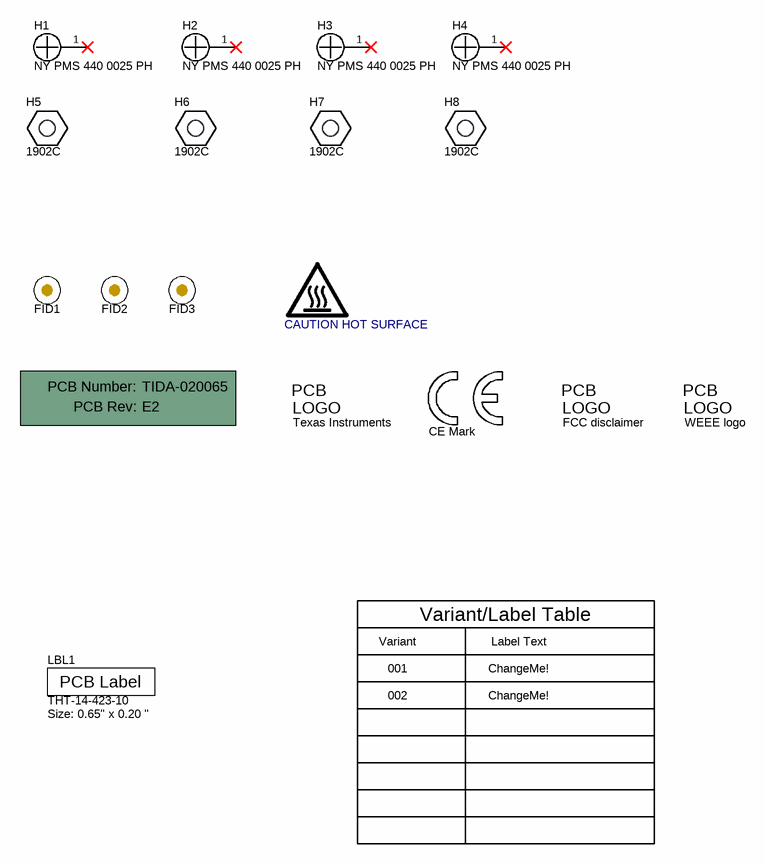
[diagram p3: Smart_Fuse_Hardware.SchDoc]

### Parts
!PCB1  Printed Circuit Board  (value not drawn)  (mechanical)
FID1  Fiducial  [Fiducial10-20]  (value not drawn)
FID2  Fiducial  [Fiducial10-20]  (value not drawn)
FID3  Fiducial  [Fiducial10-20]  (value not drawn)
H1  NY PMS 440 0025 PH  [NY PMS 440 0025 PH]
H2  NY PMS 440 0025 PH  [NY PMS 440 0025 PH]
H3  NY PMS 440 0025 PH  [NY PMS 440 0025 PH]
H4  NY PMS 440 0025 PH  [NY PMS 440 0025 PH]
H5  1902C  [Keystone_1902C]
H6  1902C  [Keystone_1902C]
H7  1902C  [Keystone_1902C]
H8  1902C  [Keystone_1902C]
LBL1  THT-14-423-10  Note: Size: 0.65" x 0.20 "  [Label_650x200]
LOGO1  CAUTION HOT SURFACE  [IEC_HotSurface_Small]  (no BOM)
Logo2  CE Mark  [CE_Mark_5mm]  (no BOM)
Logo3  Texas Instruments  [TI_Stacked_Overlay_Small]  (no BOM)
Logo4  FCC disclaimer  [FCC_disclaimer]  (no BOM)
Logo5  WEEE logo  [WEEE_Minimum]  (no BOM)

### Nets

Not connected (* = marked no-connect by the designer): H1 1*; H2 1*; H3 1*; H4 1*

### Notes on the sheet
- Variant
- Variant/Label Table
- Label Text
- 001
- 002
- ChangeMe!

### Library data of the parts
!PCB1 = CMP-0003618-2: Manufacturer: Any; PartNumber: TIDA-020065
FID1-FID3 = CMP-0077181-1: Fiducial mark.  There is nothing to buy or mount.
H1-H4 = CMP-0003617-1: Machine Screw, Round, #4-40 x 1/4, Nylon, Philips panhead; Manufacturer: B&F Fastener Supply; CompType: Hardware
H5-H8 = CMP-0003610-1: Standoff, Hex, 0.5"L #4-40 Nylon; Manufacturer: Keystone; CompType: Hardware
LBL1 = CMP-0003625-1: Thermal Transfer Printable Labels, 0.650" W x 0.200" H - 10,000 per roll; Manufacturer: Brady; CompType: Label
LOGO1 = CMP-0074837-1: IEC 61010-1 Hot Surface Warning; SymbolCreator: a0412235
Logo2 = CMP-0074844-1: SymbolCreator: a0412235
Logo3 = CMP-0074838-1: Texas Instrument Corporate Signature; SymbolCreator: a0412235; Lib Reference: TI_Logo; Library Reference: Logo
Logo4 = CMP-0074847-1: FCC_disclaimer; Library Reference: Logo
Logo5 = CMP-0074769-1

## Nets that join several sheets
3V3 LDO: Smart_Fuse_Schematic (7 pins), Smart_Fuse_MCU_Schematic (9 pins)
GND: Smart_Fuse_Schematic (32 pins), Smart_Fuse_MCU_Schematic (21 pins)
FETGOOD: Smart_Fuse_Schematic (R7.1 U2.3), Smart_Fuse_MCU_Schematic (R25.1)
FLT: Smart_Fuse_Schematic (R12.1 U3.5), Smart_Fuse_MCU_Schematic (R23.1 R23.2 R30.1 U6.21)
GPIO_INA_EN: Smart_Fuse_Schematic (TP6.1 U4.3), Smart_Fuse_MCU_Schematic (R18.1)
GPIO_INP: Smart_Fuse_Schematic (U3.3), Smart_Fuse_MCU_Schematic (J5.2 R20.1)
GPIO_LPM: Smart_Fuse_Schematic (U3.2), Smart_Fuse_MCU_Schematic (J6.2 R21.1)
GPIO_SCP_TEST: Smart_Fuse_Schematic (U3.10), Smart_Fuse_MCU_Schematic (J8.2 R22.1 R22.2 U6.20)
GPIO_WAKE: Smart_Fuse_Schematic (R13.1 U3.4), Smart_Fuse_MCU_Schematic (R17.1 R17.2 U6.15)
Ideal_Diode_EN: Smart_Fuse_Schematic (R1.1 U2.1), Smart_Fuse_MCU_Schematic (R19.1)
INA_OUT: Smart_Fuse_Schematic (TP7.1 U5.5), Smart_Fuse_MCU_Schematic (R24.1)

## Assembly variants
001: not fitted C8 D3 FID1 FID2 FID3 R9 R19
Smart Fuse with Populated Components: not fitted C8 D3 R6 R9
